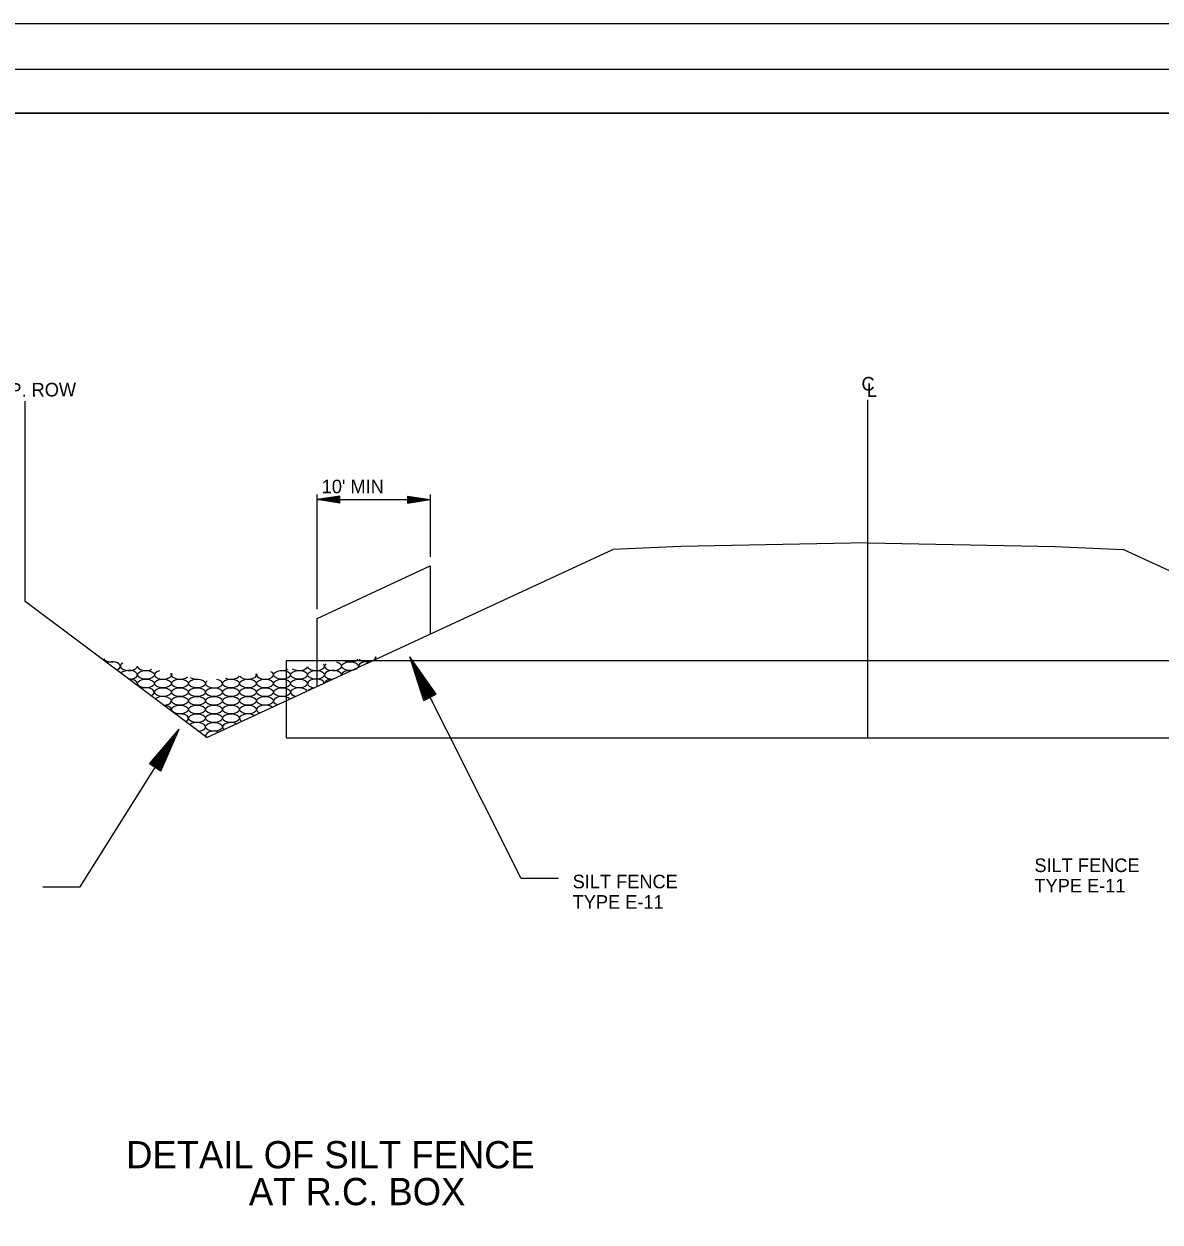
# Model space of a CAD drawing. Extents: x 3575 to 11445, y 9479 to 13278.
# Drawn here: x 6470 to 6971, y 10578 to 11106 of the extents above; entities that cross this region are included whole.
import ezdxf

# ---------------------------------------------------------------- set-up
doc = ezdxf.new("R2010")
doc.units = 0
for name, color, linetype in [('_Drafting 1', 7, 'Continuous'), ('Agg Base Course Text', 7, 'Continuous'), ('Aggregate Base Course', 7, 'Continuous'), ('CL Construction', 7, 'Continuous'), ('Default', 7, 'Continuous'), ('R_Culvert', 7, 'Continuous'), ('R_Dimension', 7, 'Continuous'), ('R_NoPlot', 7, 'Continuous'), ('R_ROW', 7, 'Continuous'), ('R_ROW Annot Labels', 7, 'Continuous'), ('STAMP_PE_CRAFTON-SIGNATURE', 7, 'Continuous'), ('STAMP_PRELIMINARY', 7, 'Continuous')]:
    doc.layers.add(name, color=color, linetype=linetype)

msp = doc.modelspace()

# ---------------------------------------------------------------- linework, layer by layer
at = {"layer": '_Drafting 1'}
msp.add_lwpolyline([(5884.86, 11066.7), (5884.86, 10039.4), (7465.76, 10039.4), (7465.76, 11002.7), (7250.26, 11002.7), (7250.26, 11001.26), (7234.07, 11001.26), (7234.07, 11017.3), (7054.46, 11017.3), (7054.46, 11066.7)], close=True, dxfattribs=at)
at = {"layer": 'Agg Base Course Text'}
for points in [[(6705.7, 10729.29), (6689.25, 10729.29), (6640.07, 10827.09)], [(6478.3, 10725.67), (6494.75, 10725.67), (6538.51, 10795.16)]]:
    msp.add_lwpolyline(points, dxfattribs=at)
at = {"layer": 'Aggregate Base Course'}
for centre, start_param, end_param in [((6501.3, 10826.77), 2.676779, 2.84111), ((6508.8, 10826.77), 0.321062, 1.959454), ((6508.8, 10822.95), 2.125862, 5.351679), ((6516.3, 10822.95), 5.510031, 9.410318), ((6598.8, 10822.95), 0.066936, 3.623187), ((6606.3, 10822.95), 5.713126, 10.543368), ((6613.8, 10826.77), 0.963635, 2.726489), ((6621.3, 10822.95), 4.392523, 6.507948), ((6621.3, 10826.77), 0.368781, 3.321342), ((6628.8, 10826.77), 6.093706, 6.656602), ((6516.3, 10819.12), 1.559845, 5.917696), ((6523.8, 10822.95), 0.014552, 2.339426), ((6531.3, 10819.12), 5.138354, 9.781995), ((6538.8, 10819.12), 5.974511, 8.945838), ((6561.3, 10819.12), 0.889662, 2.800461), ((6568.8, 10819.12), 0.30988, 3.380244), ((6576.3, 10819.12), 6.02683, 10.229664), ((6583.8, 10822.95), 1.344899, 2.345224), ((6591.3, 10822.95), 0.61675, 3.073373), ((6606.3, 10819.12), 3.075531, 7.82494), ((6613.8, 10819.12), 4.554975, 6.345496), ((6516.3, 10815.3), 2.75428, 4.723261), ((6523.8, 10811.47), 2.192031, 5.28551), ((6546.3, 10819.12), 0.626842, 1.727136), ((6553.8, 10815.3), 5.619596, 10.636898), ((6591.3, 10811.47), 3.411358, 7.489113), ((6598.8, 10815.3), 3.25379, 7.646681), ((6598.8, 10811.47), 4.986113, 5.914358), ((6606.3, 10815.3), 4.742391, 6.15808), ((6531.3, 10807.65), 1.638385, 5.839156), ((6583.8, 10807.65), 3.557164, 7.343307), ((6531.3, 10803.82), 2.836006, 4.641535), ((6576.3, 10803.82), 3.696139, 7.204332), ((6538.8, 10800), 2.258305, 5.219235), ((6546.3, 10796.17), 1.713461, 5.76408), ((6561.3, 10796.17), 3.966171, 6.9343), ((6568.8, 10800), 3.831595, 7.068876), ((6553.8, 10792.35), 4.102353, 6.726478)]:
    msp.add_ellipse(centre, major_axis=(-3.75, 0), ratio=0.51, start_param=start_param, end_param=end_param, dxfattribs=at)
for centre in [(6613.8, 10822.95), (6523.8, 10819.12), (6583.8, 10819.12), (6591.3, 10819.12), (6598.8, 10819.12), (6523.8, 10815.3), (6531.3, 10815.3), (6531.3, 10811.47), (6538.8, 10815.3), (6538.8, 10811.47), (6546.3, 10815.3), (6546.3, 10811.47), (6553.8, 10811.47), (6561.3, 10815.3), (6561.3, 10811.47), (6568.8, 10815.3), (6568.8, 10811.47), (6576.3, 10815.3), (6576.3, 10811.47), (6583.8, 10815.3), (6583.8, 10811.47), (6591.3, 10815.3), (6538.8, 10807.65), (6546.3, 10807.65), (6553.8, 10807.65), (6561.3, 10807.65), (6568.8, 10807.65), (6576.3, 10807.65), (6538.8, 10803.82), (6546.3, 10803.82), (6553.8, 10803.82), (6561.3, 10803.82), (6568.8, 10803.82), (6546.3, 10800), (6553.8, 10800), (6553.8, 10796.17), (6561.3, 10800)]:
    msp.add_ellipse(centre, major_axis=(-3.75, 0), ratio=0.51, dxfattribs=at)
at = {"layer": 'CL Construction'}
msp.add_line((6842.1, 10791.44), (6842.1, 10940.32), dxfattribs=at)
at = {"layer": 'Default'}
for p, q in [((6842.1, 10877.3), (6759.62, 10875.65)), ((6842.1, 10877.3), (6924.58, 10875.65)), ((6550.61, 10791.44), (6729.64, 10874.45)), ((6759.62, 10875.65), (6729.64, 10874.45)), ((6924.58, 10875.65), (6954.56, 10874.45)), ((7133.59, 10791.42), (6954.56, 10874.45)), ((6649.14, 10867.13), (6649.14, 10837.13)), ((6550.61, 10791.44), (6470.61, 10851.44))]:
    msp.add_line(p, q, dxfattribs=at)
msp.add_lwpolyline([(6599.34, 10814.03), (6599.34, 10844.03), (6649.14, 10867.13)], dxfattribs=at)
at = {"layer": 'R_Culvert'}
msp.add_lwpolyline([(6585.61, 10791.42), (7098.59, 10791.42), (7098.59, 10825.31), (6585.61, 10825.31)], close=True, dxfattribs=at)
at = {"layer": 'R_Dimension'}
for p, q in [((6599.34, 10848.03), (6599.34, 10898.65)), ((6609.34, 10897.88), (6599.34, 10896.38)), ((6609.34, 10897.63), (6601.01, 10896.38)), ((6609.34, 10897.38), (6602.73, 10896.38)), ((6609.34, 10894.88), (6609.34, 10897.88)), ((6639.14, 10897.88), (6649.14, 10896.38)), ((6639.14, 10897.88), (6639.14, 10894.88)), ((6639.14, 10897.63), (6647.47, 10896.38)), ((6639.14, 10897.38), (6645.75, 10896.38)), ((6649.14, 10898.65), (6649.14, 10871.13)), ((6599.34, 10896.38), (6649.14, 10896.38)), ((6609.34, 10894.88), (6599.34, 10896.38)), ((6609.34, 10895.13), (6601.01, 10896.38)), ((6609.34, 10895.39), (6602.73, 10896.38)), ((6609.34, 10897.13), (6604.39, 10896.38)), ((6609.34, 10895.64), (6604.39, 10896.38)), ((6609.34, 10896.87), (6606.09, 10896.38)), ((6609.34, 10895.9), (6606.09, 10896.38)), ((6609.34, 10896.62), (6607.76, 10896.38)), ((6609.34, 10896.15), (6607.76, 10896.38)), ((6639.14, 10897.13), (6644.09, 10896.38)), ((6639.14, 10896.87), (6642.39, 10896.38)), ((6639.14, 10896.62), (6640.72, 10896.38)), ((6639.14, 10894.88), (6649.14, 10896.38)), ((6639.14, 10895.89), (6642.39, 10896.38)), ((6639.14, 10895.39), (6645.75, 10896.38)), ((6639.14, 10895.13), (6647.47, 10896.38)), ((6639.14, 10895.64), (6644.09, 10896.38)), ((6639.14, 10896.15), (6640.72, 10896.38))]:
    msp.add_line(p, q, dxfattribs=at)
at = {"layer": 'R_NoPlot'}
msp.add_lwpolyline([(5822.82, 11086.17), (7489.52, 11086.17), (7489.52, 10019.49), (5822.82, 10019.49)], close=True, dxfattribs=at)
at = {"layer": 'R_ROW'}
msp.add_line((6470.61, 10851.44), (6470.61, 10939.74), dxfattribs=at)
at = {"layer": 'STAMP_PE_CRAFTON-SIGNATURE'}
for p, q in [((6646.37, 10807.87), (6640.07, 10827.09)), ((6651.74, 10810.57), (6640.07, 10827.09)), ((6646.82, 10808.1), (6641.57, 10824.11)), ((6651.29, 10810.34), (6641.57, 10824.11)), ((6650.83, 10810.12), (6643.12, 10821.03)), ((6647.28, 10808.33), (6643.12, 10821.03)), ((6647.72, 10808.55), (6644.61, 10818.06)), ((6650.39, 10809.89), (6644.61, 10818.06)), ((6649.93, 10809.66), (6646.13, 10815.03)), ((6648.19, 10808.79), (6646.13, 10815.03)), ((6646.37, 10807.87), (6651.74, 10810.57)), ((6649.47, 10809.43), (6647.64, 10812.04)), ((6648.63, 10809.01), (6647.64, 10812.04)), ((6525.31, 10779.83), (6538.51, 10795.16)), ((6525.73, 10779.56), (6536.73, 10792.33)), ((6529.96, 10776.9), (6536.73, 10792.33)), ((6530.39, 10776.63), (6538.51, 10795.16)), ((6526.16, 10779.29), (6534.89, 10789.42)), ((6526.59, 10779.03), (6533.12, 10786.6)), ((6529.11, 10777.44), (6533.12, 10786.6)), ((6529.53, 10777.17), (6534.89, 10789.42)), ((6527.02, 10778.75), (6531.31, 10783.73)), ((6528.67, 10777.71), (6531.31, 10783.73)), ((6530.39, 10776.63), (6525.31, 10779.83)), ((6527.45, 10778.48), (6529.53, 10780.91)), ((6528.25, 10777.98), (6529.53, 10780.91))]:
    msp.add_line(p, q, dxfattribs=at)
at = {"layer": 'STAMP_PRELIMINARY'}
for p, q in [((7488.76, 11106.1), (5728.76, 11106.1)), ((5884.86, 11066.7), (7465.76, 11066.7)), ((6647.46, 11065.4), (6647.46, 11065.4)), ((6647.46, 11065.4), (6647.46, 11065.4))]:
    msp.add_line(p, q, dxfattribs=at)

# ---------------------------------------------------------------- texts
at = {"layer": 'Agg Base Course Text'}
for s, p in [('SILT FENCE', (6915.48, 10732.17)), ('SILT FENCE', (6711.9, 10725.01)), ('TYPE E-11', (6915.48, 10723.17)), ('TYPE E-11', (6711.9, 10716.01))]:
    msp.add_text(s, height=6, dxfattribs=at).set_placement(p)
at = {"layer": 'CL Construction'}
for s, p in [('C', (6839.24, 10944.46)), ('L', (6841.53, 10941.68))]:
    msp.add_text(s, height=6, dxfattribs=at).set_placement(p)
at = {"layer": 'R_Dimension'}
msp.add_text("10' MIN", height=6, dxfattribs=at).set_placement((6601.28, 10899.17))
at = {"layer": 'R_ROW Annot Labels'}
msp.add_text('PROP. ROW', height=6, rotation=0.435, dxfattribs=at).set_placement((6446.22, 10941.6))
at = {"layer": 'STAMP_PE_CRAFTON-SIGNATURE'}
for s, p in [('DETAIL OF SILT FENCE', (6515.08, 10601.57)), ('AT R.C. BOX', (6569.2, 10585.31))]:
    msp.add_text(s, height=12, dxfattribs=at).set_placement(p)

doc.saveas('drawing.dxf')
